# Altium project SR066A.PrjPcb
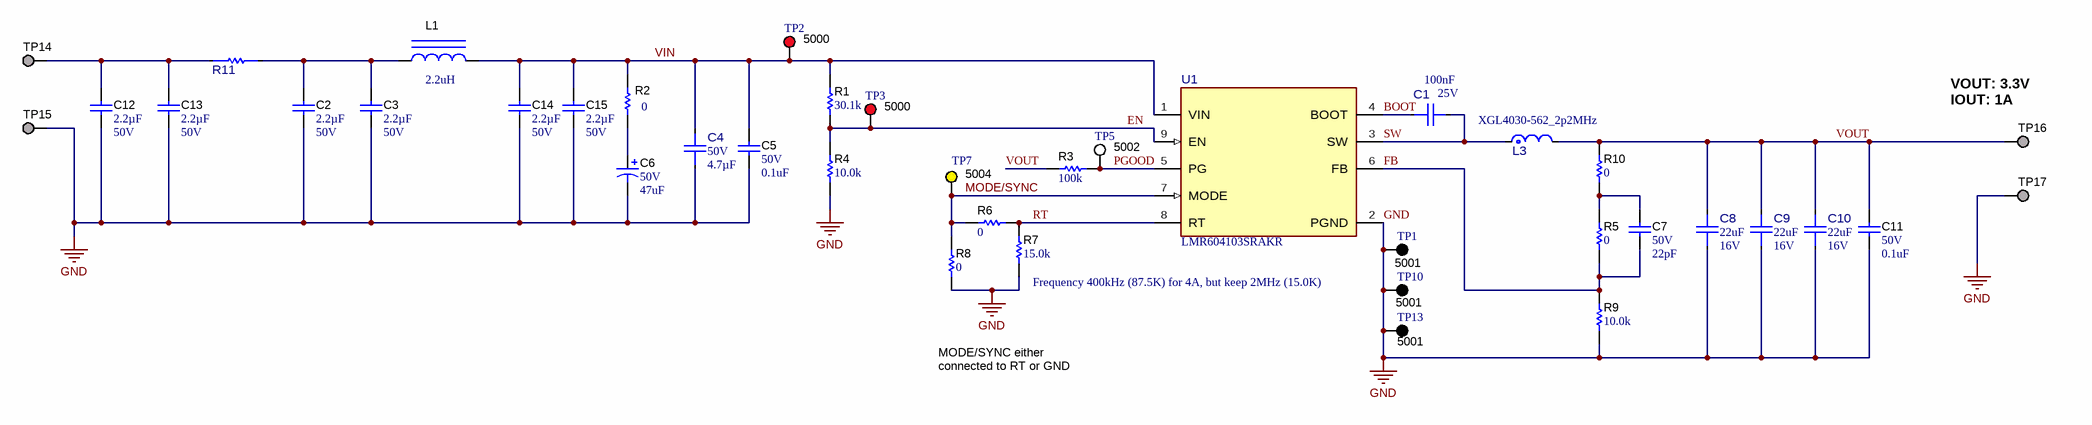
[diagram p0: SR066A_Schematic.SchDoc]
CopyrightYear: 2024; PCB_Layout: R Fu; PCB_Rev: A; PRJ_Customer: Public Release; PRJ_Engineer: R Fu; PRJ_Number: SR066; PRJ_Title: LMR60410EVM; SCH_Rev: A; TechSupport: http://www.ti.com/support; TID: N/A
2 sheets, 65 parts. Net scope: global (net labels, ports and power ports of the same name join across sheets).
Board file: SR066A.PcbDoc
Sheets:
  SR066A_Schematic.SchDoc
  SR066A_Hardware.SchDoc

## Sheet SR066A_Schematic.SchDoc: LMR604XXQEVM  Schematic
size 431 x 279 mm; Date: Not shown in title block; ApprovedBy: Not shown in title block; CheckedBy: Not shown in title block; Author: Not shown in title block; CompanyName: Not shown in title block; DrawnBy: R Fu; Engineer: Not shown in title block; Organization: Not shown in title block; Address1: Not shown in title block; Address2: Not shown in title block; Address3: Not shown in title block; Address4: Not shown in title block; DocumentNumber: 2; Revision: Use project parameter SCH_Rev; SheetNumber: 2; SheetTotal: 2; PageSetup: Record=PageOptions¦CenterHorizontal=True¦CenterVertical=True¦PrintScale=1.00¦XCorrection=1.00¦YCorrection=1.00¦PrintKind=0¦BorderSize=5000000¦LeftOffset=0¦BottomOffset=0¦Orientation=2¦PaperLength=1000¦PaperWidth=1000¦Scale=100¦PaperSource=15¦PrintQuality=600¦MediaType=1¦DitherType=10¦PaperKind=Letter¦PrintScaleMode=1

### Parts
C1  ValueDisplayed: 100nF  VDC_V: 25V  [FP-CS0402KRX7R8BB104_0402-MFG]  (hidden comment: CS0402KRX7R8BB104)
C2  Cap_F: 2.2µF  VDC_V: 50V  [0805_HV]  (hidden comment: CGA4J3X7R1H225K125AB)
C3  Cap_F: 2.2µF  VDC_V: 50V  [0805_HV]  (hidden comment: CGA4J3X7R1H225K125AB)
C4  VDC_V: 50V  Cap_F: 4.7µF  [FP-C2012X7R1H475K125AC_0805-MFG]  (hidden comment: C2012X7R1H475K125AC)
C5  VDC_V: 50V  ValueDisplayed: 0.1uF  [0402]  (hidden comment: GCM155R71H104KE02D)
C6  VDC_V: 50V  ValueDisplayed: 47uF  [Panasonic_D]  (hidden comment: EEEFT1H470AP)
C7  VDC_V: 50V  ValueDisplayed: 22pF  [0402]  (hidden comment: CGA2B2C0G1H220J050BA)
C8  ValueDisplayed: 22uF  VDC_V: 16V  [FP-CGA6P1X7R1C226M250AC_1210-MFG]  (hidden comment: CGA6P1X7R1C226M250AC)
C9  ValueDisplayed: 22uF  VDC_V: 16V  [FP-CGA6P1X7R1C226M250AC_1210-MFG]  (hidden comment: CGA6P1X7R1C226M250AC)
C10  ValueDisplayed: 22uF  VDC_V: 16V  [FP-CGA6P1X7R1C226M250AC_1210-MFG]  (hidden comment: CGA6P1X7R1C226M250AC)
C11  VDC_V: 50V  ValueDisplayed: 0.1uF  [0402]  (hidden comment: GCM155R71H104KE02D)
C12  Cap_F: 2.2µF  VDC_V: 50V  [0805_HV]  (hidden comment: CGA4J3X7R1H225K125AB)
C13  Cap_F: 2.2µF  VDC_V: 50V  [0805_HV]  (hidden comment: CGA4J3X7R1H225K125AB)
C14  Cap_F: 2.2µF  VDC_V: 50V  [0805L]  (hidden comment: CGA4J3X7R1H225K125AB)
C15  Cap_F: 2.2µF  VDC_V: 50V  [0805L]  (hidden comment: CGA4J3X7R1H225K125AB)
L1  ValueDisplayed: 2.2uH  [XEL4020]  (hidden comment: XEL4020-222MEB)
L3  XGL4030-562MEC  [FP-XGL4030-562MEC_SMT_IND_4MM0_4MM0-MFG]  (value not drawn)
R1  ValueDisplayed: 30.1k  [0402L]  (hidden comment: CRCW040230K1FKED)
R2  value 0  [0402L]  (hidden comment: RC0402JR-070RL)
R3  ValueDisplayed: 100k  [0402L]  (hidden comment: CRCW0402100KJNED)
R4  ValueDisplayed: 10.0k  [0402L]  (hidden comment: AC0402FR-0710KL)
R5  ValueDisplayed: 0  [0402L]  (hidden comment: RC0402JR-070RL)
R6  ValueDisplayed: 0  [0402L]  (hidden comment: RC0402JR-070RL)
R7  ValueDisplayed: 15.0k  [0402L]  (hidden comment: CRCW040215K0FKED)
R8  ValueDisplayed: 0  [0402L]  (hidden comment: RC0402JR-070RL)
R9  ValueDisplayed: 10.0k  [0402L]  (hidden comment: MCS0402MD1002BE100)
R10  ValueDisplayed: 0  [0402L]  (hidden comment: RC0402JR-070RL)
R11  5108  [FP-5108_1206-MFG]  (value not drawn)
TP1  5001  [Keystone5001]
TP2  5000  [Keystone5000]
TP3  5000  [Keystone5000]
TP5  5002  [Keystone5002]
TP7  5004  [Keystone5004]
TP10  5001  [Keystone5001]
TP13  5001  [Keystone5001]
TP14  1502-2  [Keystone1502-2]  (value not drawn)
TP15  1502-2  [Keystone1502-2]  (value not drawn)
TP16  1502-2  [Keystone1502-2]  (value not drawn)
TP17  1502-2  [Keystone1502-2]  (value not drawn)
U1  LMR604103SRAKR  [RAK0009A-MFG]

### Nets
GND: C2.2 C3.2 C4.1 C5.2 C6.2(-) C8.1 C9.1 C10.1 C11.2 C12.2 C13.2 C14.2 C15.2 R4.1 R7.1 R8.1 R9.1 TP1.1 TP10.1 TP13.1 TP15.1 TP17.1 U1.2(PGND)
BOOT: C1.1 U1.4(BOOT)
EN: R1.1 R4.2 TP3.1 U1.9(EN)
FB: C7.2 R5.1 R9.2 U1.6(FB)
MODE/SYNC: R6.2 R8.2 TP7.1 U1.7(MODE)
PGOOD: R3.2 TP5.1 U1.5(PG)
RT: R6.1 R7.2 U1.8(RT)
SW: C1.2 L3.1 U1.3(SW)
VIN: C4.2 C5.1 C14.1 C15.1 L1.2 R1.2 R2.2 TP2.1 U1.1(VIN)
VOUT: C8.2 C9.2 C10.2 C11.1 L3.2 R3.1 R10.2 TP16.1
NetC2_1: C2.1 C3.1 L1.1 R11.2
NetC6_1: C6.1(+) R2.1
NetC7_1: C7.1 R5.2 R10.1
NetC12_1: C12.1 C13.1 R11.1 TP14.1

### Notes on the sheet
- (near TP14) VIN: 8V-36V
- (near L3) XGL4030-562_2p2MHz
- (near TP16) VOUT: 3.3V
  IOUT: 1A
- (near R7) Frequency 400kHz (87.5K) for 4A, but keep 2MHz (15.0K)
- MODE/SYNC either connected to RT or GND

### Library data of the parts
C1 = CMP-0050130-1: 0.1 µF ±10% 25V Ceramic Capacitor X7R 0402 (1005 Metric); Manufacturer: Yageo; AEC Qualified: No; SizeZ_mm: 0.65mm; TempCo: 15%; Value: 100nF
C2 C3 C12-C15 = CMP-0007977-2: CAP, CERM, 2.2 uF, 50 V, +/- 10%, X7R, AEC-Q200 Grade 1, 0805; Manufacturer: TDK; TaMin_C: -55°C; ESR_ohm: 3.288m; Polarized: N; SizeAreaWB_mm2: 6.75; Value1: 0.003288 ohm; U/M: EA; Value: 2.2uF; TaMax_C: 125°C; SizeZ_mm: 1.45; SizeX_mm: 2; SizeY_mm: 1.25; Cap_Case: 0805; SizeArea_mm2: 2.5; AEC Qualified: Y; IRMS_A: 3.6003A; AEC Grade: 1; AEC Category: Q200
C4 = CMP-0088943-1: 4.7µF ±10% 50V Ceramic Capacitor X7R 0805 (2012 Metric); Manufacturer: TDK; TempCo: 15%; AEC Qualified: No; ValueDisplayed: 4.7uF; SizeZ_mm: 1.5mm
C5 C11 = CMP-0006356-2: CAP, CERM, 0.1 uF, 50 V, +/- 10%, X7R, AEC-Q200 Grade 1, 0402; Manufacturer: MuRata; TaMin_C: -55°C; Polarized: N; SizeAreaWB_mm2: 3; Value1: Unknown; U/M: EA; Value: 0.1uF; TaMax_C: 125°C; SizeZ_mm: 0.6; SizeX_mm: 1; SizeY_mm: 0.5; AEC Qualified: Y; Cap_F: 100nF; AEC Category: Q200
C6 = CMP-0011204-2: CAP, AL, 47 uF, 50 V, +/- 20%, 0.68 ohm, AEC-Q200 Grade 2, SMD; Manufacturer: Panasonic; TaMin_C: -55°C; ESR_ohm: 0.68; Polarized: Y; SizeAreaWB_mm2: 73.96; U/M: EA; Value: 47uF; TaMax_C: 105°C; SizeZ_mm: 6.1; SizeX_mm: 6.6; Cap_Case: 6.3x5.8mm; SizeArea_mm2: 43.56; CompType: Capacitor; Cap_F: 47µF; IRMS_A: 195mA; AEC Grade: 2; AEC Category: Q200
C7 = CMP-0860831-1: CAP, CERM, 22 pF, 50 V,+/- 5%, C0G/NP0, AEC-Q200 Grade 1, 0402; Manufacturer: TDK; AEC Grade: 1; AEC Category: Q200; TaMin_C: -55°C; SizeY_mm: 0.5; Polarized: N; U/M: EA; SizeZ_mm: 0.6; AEC Qualified: Y; SizeAreaWB_mm2: 3; TaMax_C: 125°C; Value: 22pF
C8-C10 = CMP-0043794-1: Cap Ceramic 22uF 16V X7R 20% Pad SMD 1210 +125°C Automotive T/R; Manufacturer: TDK; AEC Grade: Grade 1; AEC Qualified: Yes; Cap_F: 22µF; SizeZ_mm: 2.8mm; TempCo: 15%; Tolerance_%: 0.2%; Value: 22µF
L1 = CMP-0061079-2: Inductor, Shielded, Composite, 2.2 uH, 5.5 A, 0.0362 ohm, AEC-Q200 Grade 1, SMD; Manufacturer: Coilcraft; Isat: 5.9A @ 30% inductance drop; Irms: 5.5A @ 40C rise; SizeAreaWB_mm2: 25; DCR_ohm: 36.2m; Value: 2.2uH; Imax_A: 5.5A; SizeZ_mm: 2.1; SizeX_mm: 4; SizeArea_mm2: 16; Ind_H: 2.2µH; AEC Qualified: Y; AEC Grade: 1; AEC Category: Q200
L3 = CMP-0120190-1: 5.6 µH Shielded Molded Inductor 5.5 A 34.7mOhm Max 1616 (4040 Metric); Manufacturer: Coilcraft; AEC Grade: Grade 1; AEC Qualified: Yes; DCR_ohm: 34.7m; Ind_H: 5.6µH; Irms: 5.5A; Isat: 2A; Material: Composite; SizeZ_mm: 3.1mm; Value: 5.6uH; Self Resonant Frequency: 25MHz; Shrouded: true; TaMax_C: +125°C; TaMin_C: -40°C; Test Frequency: 1MHz; Tolerance_%: 20%
R1 = CMP-0026284-2: RES, 30.1 k, 1%, 0.063 W, AEC-Q200 Grade 0, 0402; Manufacturer: Vishay-Dale; Power_W: 63mW; TempCo: 100 ppm/C; Value_Code: 30k1; Value: 30.1k; EIA_Code: E96; SizeX_mm: 1; SizeY_mm: 0.5; SizeZ_mm: 0.6; Value2: 0.063W; AEC Qualified: Y; VDC_V: 50V; AEC Category: Q200; AEC Grade: 0
R2 = CMP-0027004-2: RES, 0, 5%, 0.063 W, 0402; Manufacturer: Yageo America; SizeZ_mm: 0.6; Power_W: 63mW; TempCo: 200 ppm/C; Value_Code: 0000; U/M: EA; EIA_Code: E24; SizeX_mm: 1; SizeY_mm: 0.5; Value2: 0.063W; VDC_V: 50V; AEC Category: Q200
R3 = CMP-0026823-3: RES, 100 k, 5%, 0.063 W, AEC-Q200 Grade 0, 0402; Manufacturer: Vishay-Dale; Power_W: 63mW; TempCo: 200 ppm/C; Value: 100k; EIA_Code: E24; SizeX_mm: 1; SizeY_mm: 0.5; SizeZ_mm: 0.6; Value2: 0.063W; AEC Qualified: Y; VDC_V: 50V; AEC Category: Q200; AEC Grade: 0
R4 = CMP-0077731-1: RES, 10.0 k, 1%, 0.063 W, AEC-Q200 Grade 0, 0402; Manufacturer: Yageo America; Power_W: 63mW; TempCo: 100 ppm/C; Value_Code: 10k0; U/M: EA; Value: 10.0k; EIA_Code: E96; Res_ohm: 10k; SizeX_mm: 1.0; SizeY_mm: 0.5; SizeZ_mm: 0.6; Value2: 0.063W; AEC Qualified: Y; VDC_V: 50V; AEC Grade: 0; AEC Category: Q200
R5 R6 R8 R10 = CMP-0027004-2: RES, 0, 5%, 0.063 W, 0402; Manufacturer: Yageo America; Power_W: 63mW; TempCo: 200 ppm/C; Value_Code: 0000; U/M: EA; Value: 0; EIA_Code: E24; SizeX_mm: 1; SizeY_mm: 0.5; SizeZ_mm: 0.6; Value2: 0.063W; VDC_V: 50V; AEC Category: Q200
R7 = CMP-0026027-3: RES, 15.0 k, 1%, 0.063 W, AEC-Q200 Grade 0, 0402; Manufacturer: Vishay-Dale; Power_W: 63mW; TempCo: 100 ppm/C; Value_Code: 15k0; Value: 15.0k; EIA_Code: E96; Res_ohm: 15k; SizeX_mm: 1; SizeY_mm: 0.5; SizeZ_mm: 0.6; Value2: 0.063W; AEC Qualified: Y; VDC_V: 50V; AEC Category: Q200; AEC Grade: 0
R9 = CMP-0077124-1: RES, 10.0 k, 0.1%, 0.1 W, AEC-Q200 Grade 0, 0402; Manufacturer: Vishay/Beyschlag; Value_Code: 10k0; SizeArea_mm2: 0.5; AEC Qualified: Y; AEC Category: Q200; Res_ohm: 10k; Value: 10.0k; SizeZ_mm: 0.6; EIA_Code: E192; TempCo: 25 ppm/C; AEC Grade: 0; Power_W: 100mW; VDC_V: 50V; Value2: 0.1W; U/M: EA; SizeX_mm: 1.0
R11 = CMP-0122408-1: 0 Ohms Jumper 0.5W, 1/2W Chip Resistor 1206 (3216 Metric) - Metal Element; Manufacturer: Keystone; AEC Qualified: No; Power_W: 500mW; Res_ohm: 0; SizeZ_mm: 0.71mm; Value: 0
TP1 TP10 TP13 = CMP-0055138-2: Test Point, Miniature, Black, TH; Manufacturer: Keystone Electronics; ContactFinish: Silver; CNHeader: FALSE; Green_Lifecycle: Active; Green_REACh: Passed; CT: TRUE
TP2 TP3 = CMP-0055137-2: Test Point, Miniature, Red, TH; Manufacturer: Keystone Electronics; Green_REACh: Passed; CT: TRUE; ContactFinish: Silver; CNHeader: FALSE; Green_Lifecycle: Active
TP5 = CMP-0055139-2: Test Point, Miniature, White, TH; Manufacturer: Keystone Electronics; ContactFinish: Silver; Green_REACh: Passed; CT: TRUE; Green_Lifecycle: Active; CNHeader: FALSE
TP7 = CMP-0055141-2: Test Point, Miniature, Yellow, TH; Manufacturer: Keystone Electronics; CT: TRUE; ContactFinish: Silver; Green_Lifecycle: Active; CNHeader: FALSE; Green_REACh: Passed
TP14-TP17 = CMP-0055113-1: Terminal, Turret, TH, Double; Manufacturer: Keystone; CT: FALSE; Green_REACh: Passed; CompType: Turret Terminal; Green_Lifecycle: Active
U1 = CMP-0123705-1: Manufacturer: Texas Instruments; SizeZ_mm: 0.8mm; AEC Qualified: No; Standoff Height: 0mm

## Sheet SR066A_Hardware.SchDoc: LMR604XXQEVM Hardware
size 431 x 279 mm; Date: Not shown in title block; ApprovedBy: Not shown in title block; CheckedBy: Not shown in title block; Author: Not shown in title block; CompanyName: Not shown in title block; DrawnBy: R Fu; Engineer: Not shown in title block; Organization: Not shown in title block; Address1: Not shown in title block; Address2: Not shown in title block; Address3: Not shown in title block; Address4: Not shown in title block; DocumentNumber: 1; Revision: Use project parameter SCH_Rev; SheetNumber: 1; SheetTotal: 2; PageSetup: Record=PageOptions¦CenterHorizontal=True¦CenterVertical=True¦PrintScale=1.00¦XCorrection=1.00¦YCorrection=1.00¦PrintKind=0¦BorderSize=5000000¦LeftOffset=0¦BottomOffset=0¦Orientation=2¦PaperLength=1000¦PaperWidth=1000¦Scale=100¦PaperSource=15¦PrintQuality=600¦MediaType=1¦DitherType=10¦PaperKind=Letter¦PrintScaleMode=1
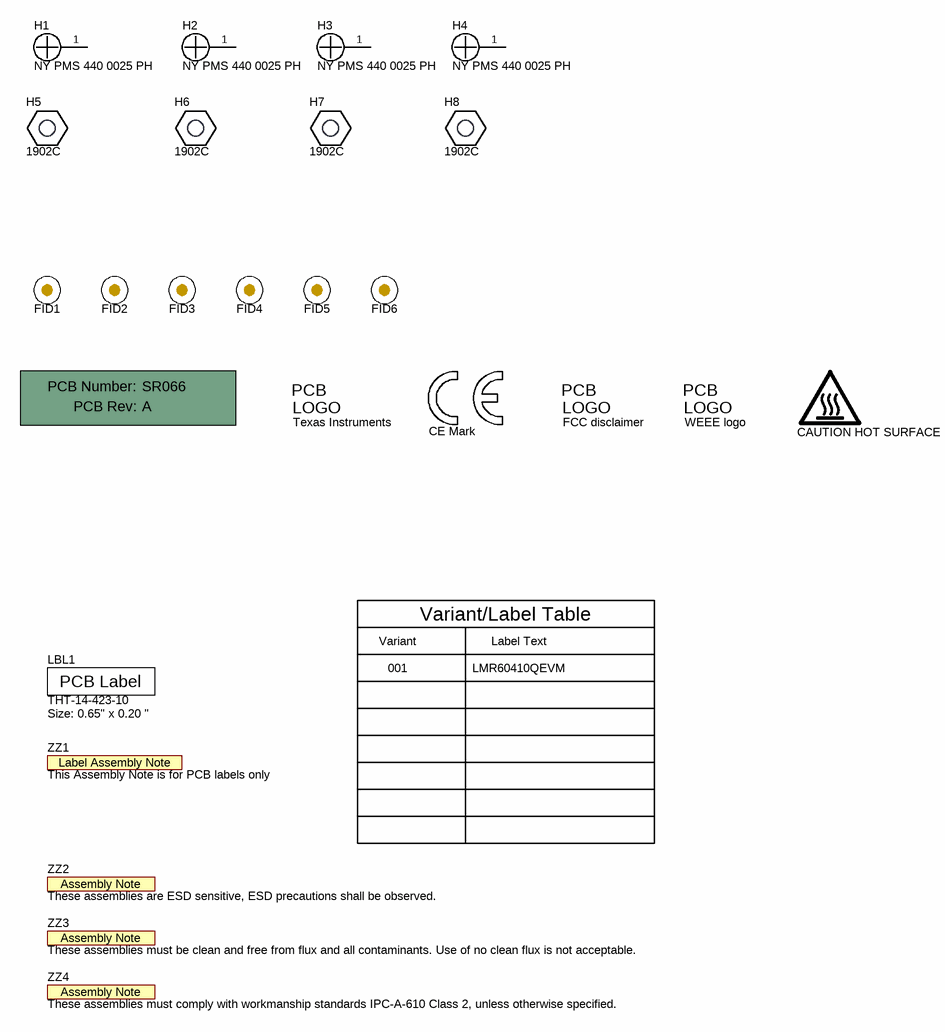
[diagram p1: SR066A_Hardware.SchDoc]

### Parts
!PCB1  Printed Circuit Board  (value not drawn)  (mechanical)
FID1  Fiducial  [Fiducial10-20]  (value not drawn)
FID2  Fiducial  [Fiducial10-20]  (value not drawn)
FID3  Fiducial  [Fiducial10-20]  (value not drawn)
FID4  Fiducial  [Fiducial10-20]  (value not drawn)
FID5  Fiducial  [Fiducial10-20]  (value not drawn)
FID6  Fiducial  [Fiducial10-20]  (value not drawn)
H1  NY PMS 440 0025 PH  [NY PMS 440 0025 PH]
H2  NY PMS 440 0025 PH  [NY PMS 440 0025 PH]
H3  NY PMS 440 0025 PH  [NY PMS 440 0025 PH]
H4  NY PMS 440 0025 PH  [NY PMS 440 0025 PH]
H5  1902C  [Keystone_1902C]
H6  1902C  [Keystone_1902C]
H7  1902C  [Keystone_1902C]
H8  1902C  [Keystone_1902C]
LBL1  THT-14-423-10  Note: Size: 0.65" x 0.20 "  [Label_650x200]
Logo1  CE Mark  [CE_Mark_5mm]  (no BOM)
Logo2  Texas Instruments  [TI_Stacked_Overlay_Small]  (no BOM)
Logo3  FCC disclaimer  [FCC_disclaimer]  (no BOM)
Logo4  WEEE logo  [WEEE_Minimum]  (no BOM)
Logo5  CAUTION HOT SURFACE  [IEC_HotSurface_Small]  (no BOM)
ZZ1  This Assembly Note is for PCB labels only  [AssemblyNoteLabel]  (no BOM)
ZZ2  These assemblies are ESD sensitive, ESD precautions shall be observed.  [AssemblyNote]  (no BOM)
ZZ3  These assemblies must be clean and free from flux and all contaminants. Use of no clean flux is not acceptable.  [AssemblyNote]  (no BOM)
ZZ4  These assemblies must comply with workmanship standards IPC-A-610 Class 2, unless otherwise specified.  [AssemblyNote]  (no BOM)

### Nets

Not connected (* = marked no-connect by the designer): H1 1; H2 1; H3 1; H4 1

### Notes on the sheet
- Variant/Label Table
- Variant
- 001
- Label Text
- LMR60410QEVM

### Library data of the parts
!PCB1 = CMP-0003618-2: Manufacturer: Any; PartNumber: SR066
FID1-FID6 = CMP-0077181-1: Fiducial mark.  There is nothing to buy or mount.
H1-H4 = CMP-0003617-1: Machine Screw, Round, #4-40 x 1/4, Nylon, Philips panhead; Manufacturer: B&F Fastener Supply; CompType: Hardware
H5-H8 = CMP-0003610-1: Standoff, Hex, 0.5"L #4-40 Nylon; Manufacturer: Keystone; CompType: Hardware
LBL1 = CMP-0003625-1: Thermal Transfer Printable Labels, 0.650" W x 0.200" H - 10,000 per roll; Manufacturer: Brady; CompType: Label
Logo1 = CMP-0074844-2: Manufacturer: Texas Instruments; SymbolCreator: a0412235; AEC Category: Q200; CompType: IC
Logo2 = CMP-0074838-1: Texas Instrument Corporate Signature; SymbolCreator: a0412235; Lib Reference: TI_Logo; Library Reference: Logo
Logo3 = CMP-0074847-1: FCC_disclaimer; Library Reference: Logo
Logo4 = CMP-0074769-4: Manufacturer: Texas Instruments; AEC Category: Q200; CompType: IC
Logo5 = CMP-0074837-2: IEC 61010-1 Hot Surface Warning; Manufacturer: Texas Instruments; CompType: IC; AEC Category: Q200; SymbolCreator: a0412235
ZZ1 = CMP-0003616-3
ZZ2 = CMP-0077236-1
ZZ3 = CMP-0077237-1
ZZ4 = CMP-0077238-1

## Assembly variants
001: not fitted C7 C8 C10 LBL1 R4 R8 R9 TP2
